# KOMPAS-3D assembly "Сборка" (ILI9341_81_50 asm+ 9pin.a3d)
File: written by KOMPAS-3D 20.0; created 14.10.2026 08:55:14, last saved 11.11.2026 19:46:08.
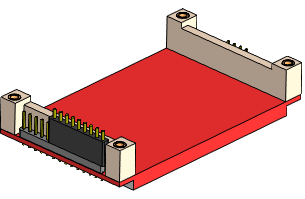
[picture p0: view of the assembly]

Document properties: Полное имя файла: D:\myProjects\Progect_esp32\box_compas\монитор\ILI9341_81_50 asm+ 9pin.a3d

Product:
- Part/product: Сборка
    Масса: 0.156395
  - Component [detail]: Деталь  | Масса: 0.00276261; source file: ..\разъемы\pbs_9.m3d
  - Component [assembly]: Сборка  | qty 2  | Масса: 0.0139528; source file: ..\корпус\п-стойка_1 asm.a3d
  - Component [detail]: Деталь  | Масса: 0.123412; source file: ILI9341_81х50.m3d
  - Component [detail]: Деталь  | Масса: 0.00180884; source file: ..\разъемы\pls_14.m3d
  - Component [detail]: Деталь  | Масса: 0.000505328; source file: ..\разъемы\pls_4.m3d

Referenced files in D:\myProjects\Progect_esp32\box_compas\монитор\: ILI9341_81х50.m3d
Referenced files in D:\myProjects\Progect_esp32\box_compas\разъемы\: pls_14.m3d, pls_4.m3d, pbs_9.m3d
Referenced files in D:\myProjects\Progect_esp32\box_compas\корпус\: п-стойка_1 asm.a3d
Referenced files in D:\RicWork\Project-EPS32\box_compas\корпус\: п-стойка_1 asm.a3d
